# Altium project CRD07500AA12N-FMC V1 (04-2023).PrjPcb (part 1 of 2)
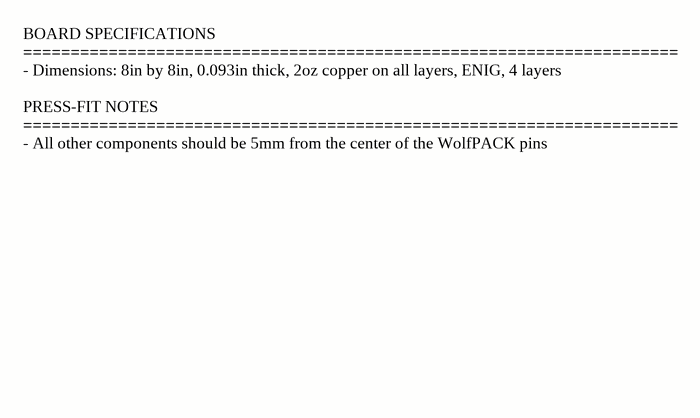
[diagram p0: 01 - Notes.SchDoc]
6 sheets, 393 parts. Net scope: global (net labels, ports and power ports of the same name join across sheets).
Board file: CRD07500AA12N-FMC V1 (04-2023).PcbDoc
Sheets:
  01 - Notes.SchDoc
  02 - Power Stage.SchDoc
  03 - Controller.SchDoc
  04 - Gate Drivers.SchDoc
  05 - Sense.SchDoc
  06 - Auxiliary Power.SchDoc

## Sheet 01 - Notes.SchDoc: 7.5kW WolfPACK FM3 Six-Pack Motor Drive
size 431 x 279 mm; Date: 04/2023; DocumentNumber: CRD07500AA12N-FMC; Revision: 1; SheetNumber: 1; SheetTotal: 6; SheetSize: B

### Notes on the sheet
- BOARD SPECIFICATIONS
  =====================================================================
  - Dimensions: 8in by 8in, 0.093in thick, 2oz copper on all layers, ENIG, 4 layers
  PRESS-FIT NOTES
  =====================================================================
  - All other components should be 5mm from the center of the WolfPACK pins

## Sheet 02 - Power Stage.SchDoc: Power Stage - 7.5kW WolfPACK Six-Pack M. Drive
size 431 x 279 mm; Date: 04/2023; DocumentNumber: CRD07500AA12N-FMC; Revision: 1; SheetNumber: 2; SheetTotal: 6; SheetSize: B
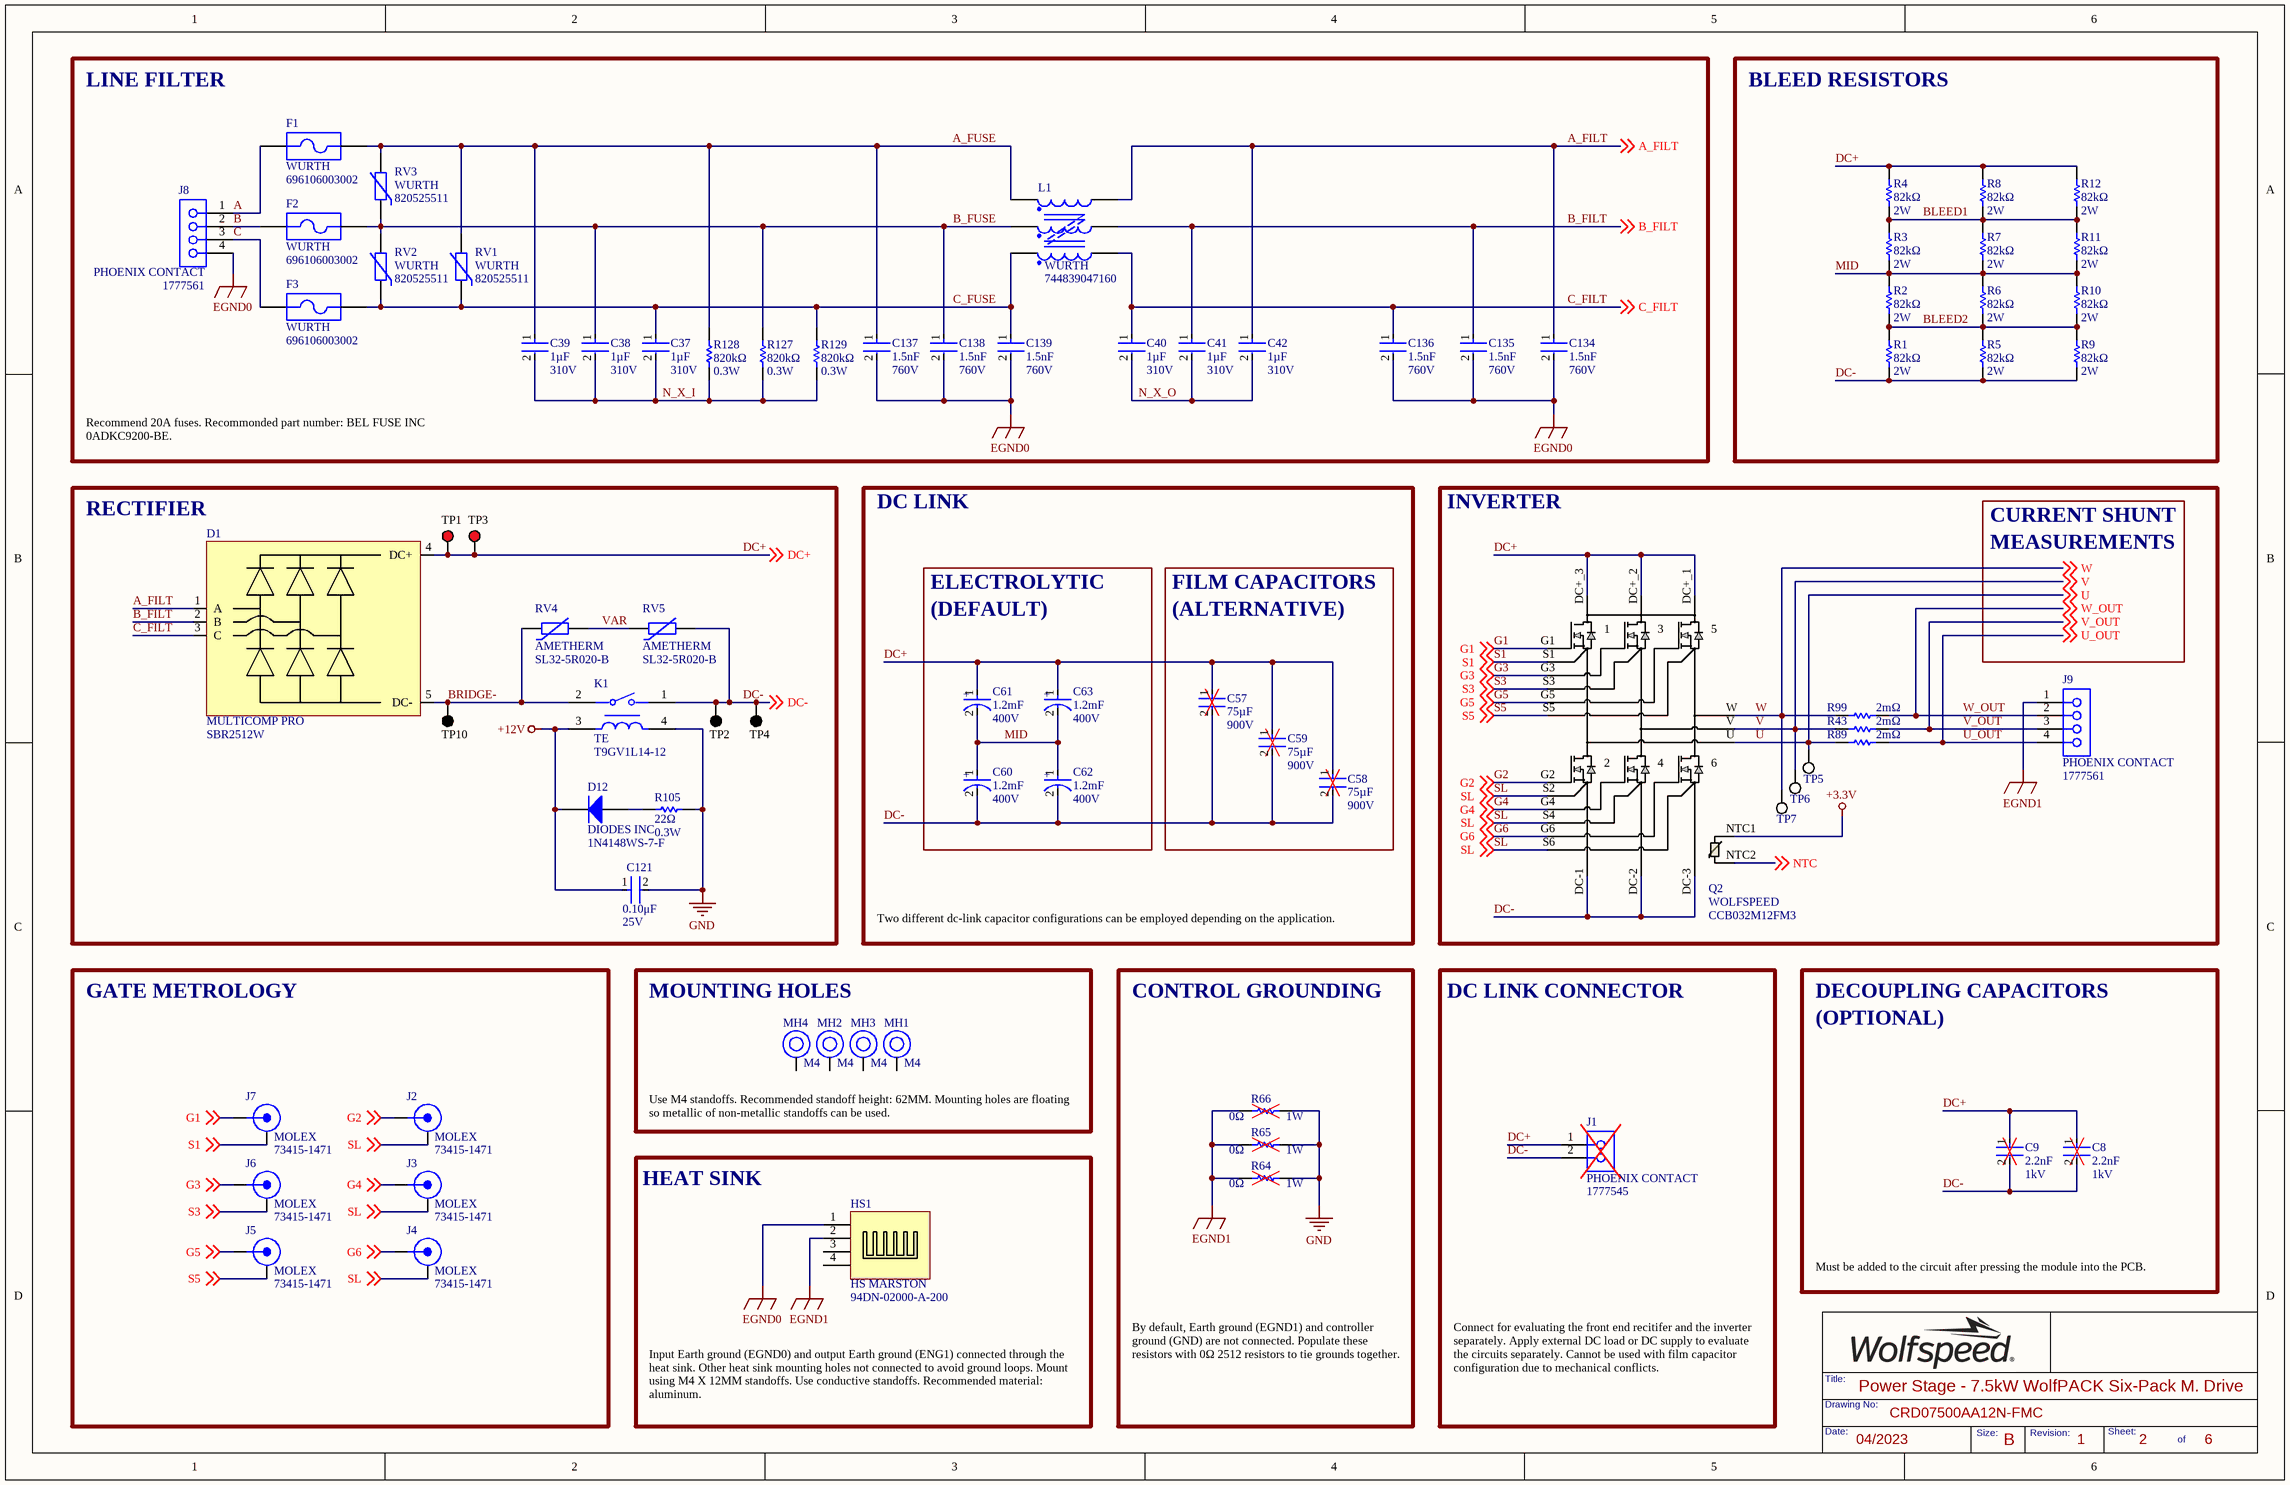
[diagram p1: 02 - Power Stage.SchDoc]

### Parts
C8  Capacitance: 2.2nF  Voltage Rating (DC): 1kV  [CAP_LDE_QD_1220_KEM]  (hidden comment: LDEQD1220KA5N00)
C9  Capacitance: 2.2nF  Voltage Rating (DC): 1kV  [CAP_LDE_QD_1220_KEM]  (hidden comment: LDEQD1220KA5N00)
C37  Capacitance: 1µF  Voltage Rating (AC): 310V  [WCAP-FTXX_L26W11H20_CS]  (hidden comment: 890334026027CS)
C38  Capacitance: 1µF  Voltage Rating (AC): 310V  [WCAP-FTXX_L26W11H20_CS]  (hidden comment: 890334026027CS)
C39  Capacitance: 1µF  Voltage Rating (AC): 310V  [WCAP-FTXX_L26W11H20_CS]  (hidden comment: 890334026027CS)
C40  Capacitance: 1µF  Voltage Rating (AC): 310V  [WCAP-FTXX_L26W11H20_CS]  (hidden comment: 890334026027CS)
C41  Capacitance: 1µF  Voltage Rating (AC): 310V  [WCAP-FTXX_L26W11H20_CS]  (hidden comment: 890334026027CS)
C42  Capacitance: 1µF  Voltage Rating (AC): 310V  [WCAP-FTXX_L26W11H20_CS]  (hidden comment: 890334026027CS)
C57  Capacitance: 75µF  Rated Voltage (DC): 900V  [WCAP-FTDB_L57W45H65]  (hidden comment: 75µF, 900V)
C58  Capacitance: 75µF  Rated Voltage (DC): 900V  [WCAP-FTDB_L57W45H65]  (hidden comment: 75µF, 900V)
C59  Capacitance: 75µF  Rated Voltage (DC): 900V  [WCAP-FTDB_L57W45H65]  (hidden comment: 75µF, 900V)
C60  Capacitance: 1.2mF  Voltage Rating: 400V  [B43630A9128M000]  (hidden comment: B43630A9128M000)
C61  Capacitance: 1.2mF  Voltage Rating: 400V  [B43630A9128M000]  (hidden comment: B43630A9128M000)
C62  Capacitance: 1.2mF  Voltage Rating: 400V  [B43630A9128M000]  (hidden comment: B43630A9128M000)
C63  Capacitance: 1.2mF  Voltage Rating: 400V  [B43630A9128M000]  (hidden comment: B43630A9128M000)
C121  Voltage Rating: 25V  Capacitance: 0.10μF  [FP-C0603C-CF-IPC_B]  (hidden comment: C0603C104K3RACTU)
C134  value 1.5nF  Voltage: 760V  [CAP_MY5UCR_VIS]  (hidden comment: SMDY1152MY5UCR)
C135  value 1.5nF  Voltage: 760V  [CAP_MY5UCR_VIS]  (hidden comment: SMDY1152MY5UCR)
C136  value 1.5nF  Voltage: 760V  [CAP_MY5UCR_VIS]  (hidden comment: SMDY1152MY5UCR)
C137  value 1.5nF  Voltage: 760V  [CAP_MY5UCR_VIS]  (hidden comment: SMDY1152MY5UCR)
C138  value 1.5nF  Voltage: 760V  [CAP_MY5UCR_VIS]  (hidden comment: SMDY1152MY5UCR)
C139  value 1.5nF  Voltage: 760V  [CAP_MY5UCR_VIS]  (hidden comment: SMDY1152MY5UCR)
D1  Manufacturer: MULTICOMP PRO  [SBR2512W]  (hidden comment: SBR2512W)
D12  Manufacturer: DIODES INC  [DIOD-SOD323-2-A_V]  (hidden comment: 1N4148WS-7-F)
F1  Manufacturer: WURTH  [696106003002]  (hidden comment: 696106003002)
F2  Manufacturer: WURTH  [696106003002]  (hidden comment: 696106003002)
F3  Manufacturer: WURTH  [696106003002]  (hidden comment: 696106003002)
HS1  Manufacturer: HS MARSTON  [94DN-02000-A-200]  (hidden comment: 94DN-02000-A-200)
J1  Manufacturer: PHOENIX CONTACT  [1777545]  (hidden comment: 1777545)
J2  Manufacturer: MOLEX  Manufacturer Part Number: 73415-1471  [FP-73415-1471-MFG]  (hidden comment: 0734151471)
J3  Manufacturer: MOLEX  Manufacturer Part Number: 73415-1471  [FP-73415-1471-MFG]  (hidden comment: 0734151471)
J4  Manufacturer: MOLEX  Manufacturer Part Number: 73415-1471  [FP-73415-1471-MFG]  (hidden comment: 0734151471)
J5  Manufacturer: MOLEX  Manufacturer Part Number: 73415-1471  [FP-73415-1471-MFG]  (hidden comment: 0734151471)
J6  Manufacturer: MOLEX  Manufacturer Part Number: 73415-1471  [FP-73415-1471-MFG]  (hidden comment: 0734151471)
J7  Manufacturer: MOLEX  Manufacturer Part Number: 73415-1471  [FP-73415-1471-MFG]  (hidden comment: 0734151471)
J8  Manufacturer: PHOENIX CONTACT  [1777561]  (hidden comment: 1777561)
J9  Manufacturer: PHOENIX CONTACT  [1777561]  (hidden comment: 1777561)
K1  Manufacturer: TE  [FP-T9GV1L14-12-MFG]  (hidden comment: T9GV1L14-12)
L1  Manufacturer: WURTH  [WE-TPB HV_Type 4XL_744839047160]  (hidden comment: 47mH)
MH1  Size: M4  [MH_M4_P]  (hidden comment: MH_M4_P)
MH2  Size: M4  [MH_M4_P]  (hidden comment: MH_M4_P)
MH3  Size: M4  [MH_M4_P]  (hidden comment: MH_M4_P)
MH4  Size: M4  [MH_M4_P]  (hidden comment: MH_M4_P)
Q2  CCB032M12FM3  Manufacturer: WOLFSPEED  [FM3_SIX-PACK_3PHASE_CRW]
R1  value 82kΩ  Power: 2W  [FP-CRGP2512-IPC_C]  (hidden comment: CRGP2512F82K)
R2  value 82kΩ  Power: 2W  [FP-CRGP2512-IPC_C]  (hidden comment: CRGP2512F82K)
R3  value 82kΩ  Power: 2W  [FP-CRGP2512-IPC_C]  (hidden comment: CRGP2512F82K)
R4  value 82kΩ  Power: 2W  [FP-CRGP2512-IPC_C]  (hidden comment: CRGP2512F82K)
R5  value 82kΩ  Power: 2W  [FP-CRGP2512-IPC_C]  (hidden comment: CRGP2512F82K)
R6  value 82kΩ  Power: 2W  [FP-CRGP2512-IPC_C]  (hidden comment: CRGP2512F82K)
R7  value 82kΩ  Power: 2W  [FP-CRGP2512-IPC_C]  (hidden comment: CRGP2512F82K)
R8  value 82kΩ  Power: 2W  [FP-CRGP2512-IPC_C]  (hidden comment: CRGP2512F82K)
R9  value 82kΩ  Power: 2W  [FP-CRGP2512-IPC_C]  (hidden comment: CRGP2512F82K)
R10  value 82kΩ  Power: 2W  [FP-CRGP2512-IPC_C]  (hidden comment: CRGP2512F82K)
R11  value 82kΩ  Power: 2W  [FP-CRGP2512-IPC_C]  (hidden comment: CRGP2512F82K)
R12  value 82kΩ  Power: 2W  [FP-CRGP2512-IPC_C]  (hidden comment: CRGP2512F82K)
R43  Resistance: 2mΩ  [FP-RC2512-0_65-MFG]  (hidden comment: CRE2512-FZ-R002E-3)
R64  Resistance: 0Ω  Max Power Dissipation: 1W  [FP-RC2512-0_65-IPC_A]  (hidden comment: RC2512JK-070RL)
R65  Resistance: 0Ω  Max Power Dissipation: 1W  [FP-RC2512-0_65-IPC_A]  (hidden comment: RC2512JK-070RL)
R66  Resistance: 0Ω  Max Power Dissipation: 1W  [FP-RC2512-0_65-IPC_A]  (hidden comment: RC2512JK-070RL)
R89  Resistance: 2mΩ  [FP-RC2512-0_65-MFG]  (hidden comment: CRE2512-FZ-R002E-3)
R99  Resistance: 2mΩ  [FP-RC2512-0_65-MFG]  (hidden comment: CRE2512-FZ-R002E-3)
R105  Resistance: 22Ω  Max Power Dissipation: 0.3W  [FP-CSR1206-IPC_A]  (hidden comment: RMCF1206FT22R0)
R127  Resistance: 820kΩ  Max Power Dissipation: 0.3W  [RESC3125X70X40LL20T20]  (hidden comment: KTR25JZPF8203)
R128  Resistance: 820kΩ  Max Power Dissipation: 0.3W  [RESC3125X70X40LL20T20]  (hidden comment: KTR25JZPF8203)
R129  Resistance: 820kΩ  Max Power Dissipation: 0.3W  [RESC3125X70X40LL20T20]  (hidden comment: KTR25JZPF8203)
RV1  Manufacturer: WURTH  [D23W10.1H27P3.4]  (hidden comment: 550VAC, 745VDC)
RV2  Manufacturer: WURTH  [D23W10.1H27P3.4]  (hidden comment: 550VAC, 745VDC)
RV3  Manufacturer: WURTH  [D23W10.1H27P3.4]  (hidden comment: 550VAC, 745VDC)
RV4  Manufacturer: AMETHERM  Manufacturer Part Number: SL32-5R020-B  [SL22 10008-B-Footprint-1]  (hidden comment: SL32 5R020-B)
RV5  Manufacturer: AMETHERM  Manufacturer Part Number: SL32-5R020-B  [SL22 10008-B-Footprint-1]  (hidden comment: SL32 5R020-B)
TP1  5010  [KSTN-5010_V]  (value not drawn)
TP2  5011  [KSTN-5011_V]  (value not drawn)
TP3  5010  [KSTN-5010_V]  (value not drawn)
TP4  5011  [KSTN-5011_V]  (value not drawn)
TP5  5012  [KSTN-5012_V]  (value not drawn)
TP6  5012  [KSTN-5012_V]  (value not drawn)
TP7  5012  [KSTN-5012_V]  (value not drawn)
TP10  5011  [KSTN-5011_V]  (value not drawn)

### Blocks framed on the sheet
LINE FILTER: C37-C42 C134-C139 F1-F3 J8 L1 R127-R129 RV1-RV3
BLEED RESISTORS: R1-R12
RECTIFIER: C121 D1 D12 K1 R105 RV4 RV5 TP1-TP4 TP10
GATE METROLOGY: J2-J7
MOUNTING HOLES: MH1-MH4
CONTROL GROUNDING: R64-R66
DC LINK CONNECTOR: J1
HEAT SINK: HS1

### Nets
+3.3V: Q2.NTC1
+12V: C121.1 D12.2(K) K1.3
EGND0: C134.2 C135.2 C136.2 C137.2 C138.2 C139.2 HS1.1 J8.4
EGND1: HS1.2 J9.1 R64.1 R65.1 R66.1
GND: C121.2 K1.4 R64.2 R65.2 R66.2 R105.2
A: F1.1 J8.1
A_FILT: C42.1 C134.1 D1.1(A) L1.4 ; off-sheet A_FILT
A_FUSE: C39.1 C137.1 F1.2 L1.1 R128.2 RV1.2 RV3.2
B: F2.1 J8.2
B_FILT: C41.1 C135.1 D1.2(B) L1.5 ; off-sheet B_FILT
B_FUSE: C38.1 C138.1 F2.2 L1.2 R127.2 RV2.2 RV3.1
BLEED1: R3.2 R4.1 R7.2 R8.1 R11.2 R12.1
BLEED2: R1.2 R2.1 R5.2 R6.1 R9.2 R10.1
BRIDGE-: D1.5(DC-) K1.2 RV4.1 TP10.1
C: F3.1 J8.3
C_FILT: C40.1 C136.1 D1.3(C) L1.6 ; off-sheet C_FILT
C_FUSE: C37.1 C139.1 F3.2 L1.3 R129.2 RV1.1 RV2.1
DC+: C8.1 C9.1 C57.1 C58.1 C59.1 C61.1 C63.1 D1.4(DC+) J1.1 Q2.DC+_1 Q2.DC+_2 Q2.DC+_3 R4.2 R8.2 R12.2 TP1.1 TP3.1 ; off-sheet DC+
DC-: C8.2 C9.2 C57.2 C58.2 C59.2 C60.2 C62.2 J1.2 K1.1 Q2.DC-1 Q2.DC-2 Q2.DC-3 R1.1 R5.1 R9.1 RV5.2 TP2.1 TP4.1 ; off-sheet DC-
G1: J7.1(CENTER) Q2.G1 ; off-sheet G1
G2: J2.1(CENTER) Q2.G2 ; off-sheet G2
G3: J6.1(CENTER) Q2.G3 ; off-sheet G3
G4: J3.1(CENTER) Q2.G4 ; off-sheet G4
G5: J5.1(CENTER) Q2.G5 ; off-sheet G5
G6: J4.1(CENTER) Q2.G6 ; off-sheet G6
MID: C60.1 C61.2 C62.1 C63.2 R2.2 R3.1 R6.2 R7.1 R10.2 R11.1
N_X_I: C37.2 C38.2 C39.2 R127.1 R128.1 R129.1
N_X_O: C40.2 C41.2 C42.2
NTC: Q2.NTC2 ; off-sheet NTC
S1: J7.2,3,4,5(SHIELD) Q2.S1 ; off-sheet S1
S3: J6.2,3,4,5(SHIELD) Q2.S3 ; off-sheet S3
S5: J5.2,3,4,5(SHIELD) Q2.S5 ; off-sheet S5
SL: J2.2,3,4,5(SHIELD) J3.2,3,4,5(SHIELD) J4.2,3,4,5(SHIELD) Q2.S2 Q2.S4 Q2.S6 ; off-sheet SL
U: Q2.U R89.1 TP5.1 ; off-sheet U
U_OUT: J9.4 R89.2 ; off-sheet U_OUT
V: Q2.V R43.1 TP6.1 ; off-sheet V
V_OUT: J9.3 R43.2 ; off-sheet V_OUT
VAR: RV4.2 RV5.1
W: Q2.W R99.1 TP7.1 ; off-sheet W
W_OUT: J9.2 R99.2 ; off-sheet W_OUT
NetD12_1: D12.1(A) R105.1

Not connected (* = marked no-connect by the designer): HS1 3 4; MH1 1; MH2 1; MH3 1; MH4 1

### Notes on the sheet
- Recommend 20A fuses. Recommonded part number: BEL FUSE INC 0ADKC9200-BE.
- DC LINK
- INVERTER
- CURRENT SHUNT
- MEASUREMENTS
- ELECTROLYTIC
- (DEFAULT)
- FILM CAPACITORS
- (ALTERNATIVE)
- Two different dc-link capacitor configurations can be employed depending on the application.
- DECOUPLING CAPACITORS
- (OPTIONAL)
- Use M4 standoffs. Recommended standoff height: 62MM. Mounting holes are floating so metallic of non-metallic standoffs can be used.
- Must be added to the circuit after pressing the module into the PCB.
- Input Earth ground (EGND0) and output Earth ground (ENG1) connected through the heat sink. Other heat sink mounting holes not connected to avoid ground loops. Mount using M4 X 12MM standoffs. Use conductive standoffs. Recommended material: aluminum.
- By default, Earth ground (EGND1) and controller ground (GND) are not connected. Populate these resistors with 0Ω 2512 resistors to tie grounds together.
- Connect for evaluating the front end recitifer and the inverter separately. Apply external DC load or DC supply to evaluate the circuits separately. Cannot be used with film capacitor configuration due to mechanical conflicts.

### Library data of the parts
C8 C9 = LDEQD1220KA5N00: CAP FILM 2200PF 10% 1KVDC 2220; Manufacturer: KEMET; Dielectric Material: Polyester; Voltage Rating (AC): 250V; Value: 2.2nF
C37-C42 = 890334026027CS: CAP FILM 1UF 10% 310VAC RADIAL; Manufacturer: WURTH; Dielectric Material: PP; Ratings: X2; Value: 1µF
C57-C59 = 890724429010CS: WCAP-FTDB DC-LINK CAPACITOR (MKP; Manufacturer: WURTH; Dissipation Factor @1kHz: 0.31%; Insulation Resistance: 133.33MΩ; Pitch: 52.5mm; Rate of Voltage Rise: 15V/µs; Technical Reference: MDBP525756J900DCPP15040
C60-C63 = B43630A9128M000: CAP ALUM 1200UF 20% 400V SNAP; Manufacturer: TDK; Polarity: Polar; ESR (Equivalent Series Resistance): 100mR; Life (Hours): 2000Hour; Impedance: 170mR; Value: 1.2mF
C121 = CMP-2006-03057-2: CAP CER 0.1UF 25V X7R 0603; Manufacturer: KEMET; Value: 0.10μF; Material: Ceramic; Tolerance: 0.1; Temperature Coefficient: 30ppm/°C; Automotive Grade: Grade 1
C134-C139 = SMDY1152MY5UCR: SMDY1 X760Y500VAC 1500PF 20% Y5U; Manufacturer: VISHAY; Description: Ceramic Suppression Cap, 1500PF, X1/Y1 Rohs Compliant: Yes
D1 = SBR2512W: BRIDGE RECT 3P 1.2KV 25A
D12 = CMP-1667-00004-1: DIODE GEN PURP 75V 150MA SOD323
F1-F3 = CMP-1502-00235-1: FUSEHOLDER BLOCKS - PCB - CLIP C; Fuse Size: 5x20mm
HS1 = 94DN-02000-A-200: HEATSINK EXTRUSION 200MM; Natural Thermal Resistance: 0.7°C/W
J1 = 1777545: TERM BLK 2P SIDE ENT 6.35MM PCB; Voltage Rating: 1kV; Voltage: 600V; Current Rating: 41A; Number of Levels: 1; Number of Positions Per Level: 2; Current: 30A; Gender: Male; Connector Type: Screw; Wire Gauge (Max): 30AWG; Wire Gauge (Min): 10AWG; Approvals: cULus,EAC
J2-J7 = 0734151471: CONN MMCX JACK STR 50 OHM PCB; Body Material: Brass; Body Plating: Gold; Impedance: 50R; Connector Type: PCB,MMCX,Coaxial; Max Frequency: 6GHz; Gender: Female
J8 J9 = 1777561: TERM BLK 4P SIDE ENT 6.35MM PCB; Current Rating: 41A; Number of Positions: 4; Voltage Rating: 1kV; Number of Levels: 1; Current: 30A; Voltage: 600V; Wire Gauge (Max): 30AWG; Wire Gauge (Min): 10AWG
K1 = CMP-03395-000345-1: RELAY GEN PURPOSE SPST 30A 12V; Operate Time: 15ms; Coil Power: 900mW; Release Time: 22ms; Coil Resistance: 160R; Relay Type: General Purpose; Coil Type: Non-Latching; Coil Current: 75mA
L1 = 744839047160: CMC 47MH 16A 3LN TH; Match Code: WE-TPB HV; Case/Size Code: Type 4XL; DC Resistance Max: 14mΩ; Insulation Test Voltage (AC): 3000V; Material: MnZn; Rated Voltage (AC): 760V
MH1-MH4 = MH_M4_P: HEX STANDOFF M4 ALUMINUM 31MM F-F; Manufacturer: MCMASTER-CARR; Manufacturer Part Number: 95947A065
Q2 = CCB032M12FM3: 1200V SIC 6-PACK MODULE; Type: DEV
R1-R12 = CRGP2512F82K: RES 82K OHM 1% 2W 2512; Manufacturer: TE
R43 R89 R99 = CRE2512-FZ-R002E-3: RES 0.002 OHM 1% 3W 2512; Manufacturer: BOURNS; Temperature Coefficient: 75ppm/°C; Value: 2mΩ
R64-R66 = RC2512JK-070RL: RES 0 OHM JUMPER 1W 2512; Manufacturer: YAGEO; Tolerance: 5%; Temperature Coefficient: 200ppm/°C; Voltage Rating: 200V; Value: 0Ω
R105 = RMCF1206FT22R0: RES 22 OHM 1% 1/4W 1206; Manufacturer: STACKPOLE; Temperature Coefficient: 100ppm/°C; Value: 22Ω
R127-R129 = KTR25JZPF8203: RES SMD 820K OHM 1% 1/3W 1210; Manufacturer: ROHM; Temperature Coefficient: 100ppm/°C; Value: 820kΩ
RV1-RV3 = 820525511: DISK VARISTOR STANDARD WE-VD - B; Channel Input Capacitance: 430pF; Clamping Voltage: 1500V; Energy Absorption: 408J; Operating Voltage (AC): 550V; Operating Voltage (DC): 745V; Pitch: 3.4mm; Power Dissipation: 1W; (Reverse) Breakdown Voltage: 910V; (Reverse) Peak Pulse Current: 6500A
RV4 RV5 = SL32 5R020-B: ICL 5 OHM 20% 20A 31MM; Resistance: 5R; Dissipation Factor: 45.4%; Lead Diameter: 1mm; Approvals: CSA,UR; Value: 5Ω
TP1 TP3 = CMP-1672-00002-4: PC TEST POINT MULTIPURPOSE RED; Manufacturer: KEYSTONE
TP2 TP4 TP10 = CMP-1672-00003-4: PC TEST POINT MULTIPURPOSE BLACK; Manufacturer: KEYSTONE
TP5-TP7 = CMP-1672-00004-4: PC TEST POINT MULTIPURPOSE WHITE; Manufacturer: KEYSTONE

## Sheet 03 - Controller.SchDoc: Controller - 7.5kW WolfPACK FM3 Six-Pack M. Drive
size 431 x 279 mm; Date: 04/2023; DocumentNumber: CRD07500AA12N-FMC; Revision: 1; SheetNumber: 3; SheetTotal: 6; SheetSize: B
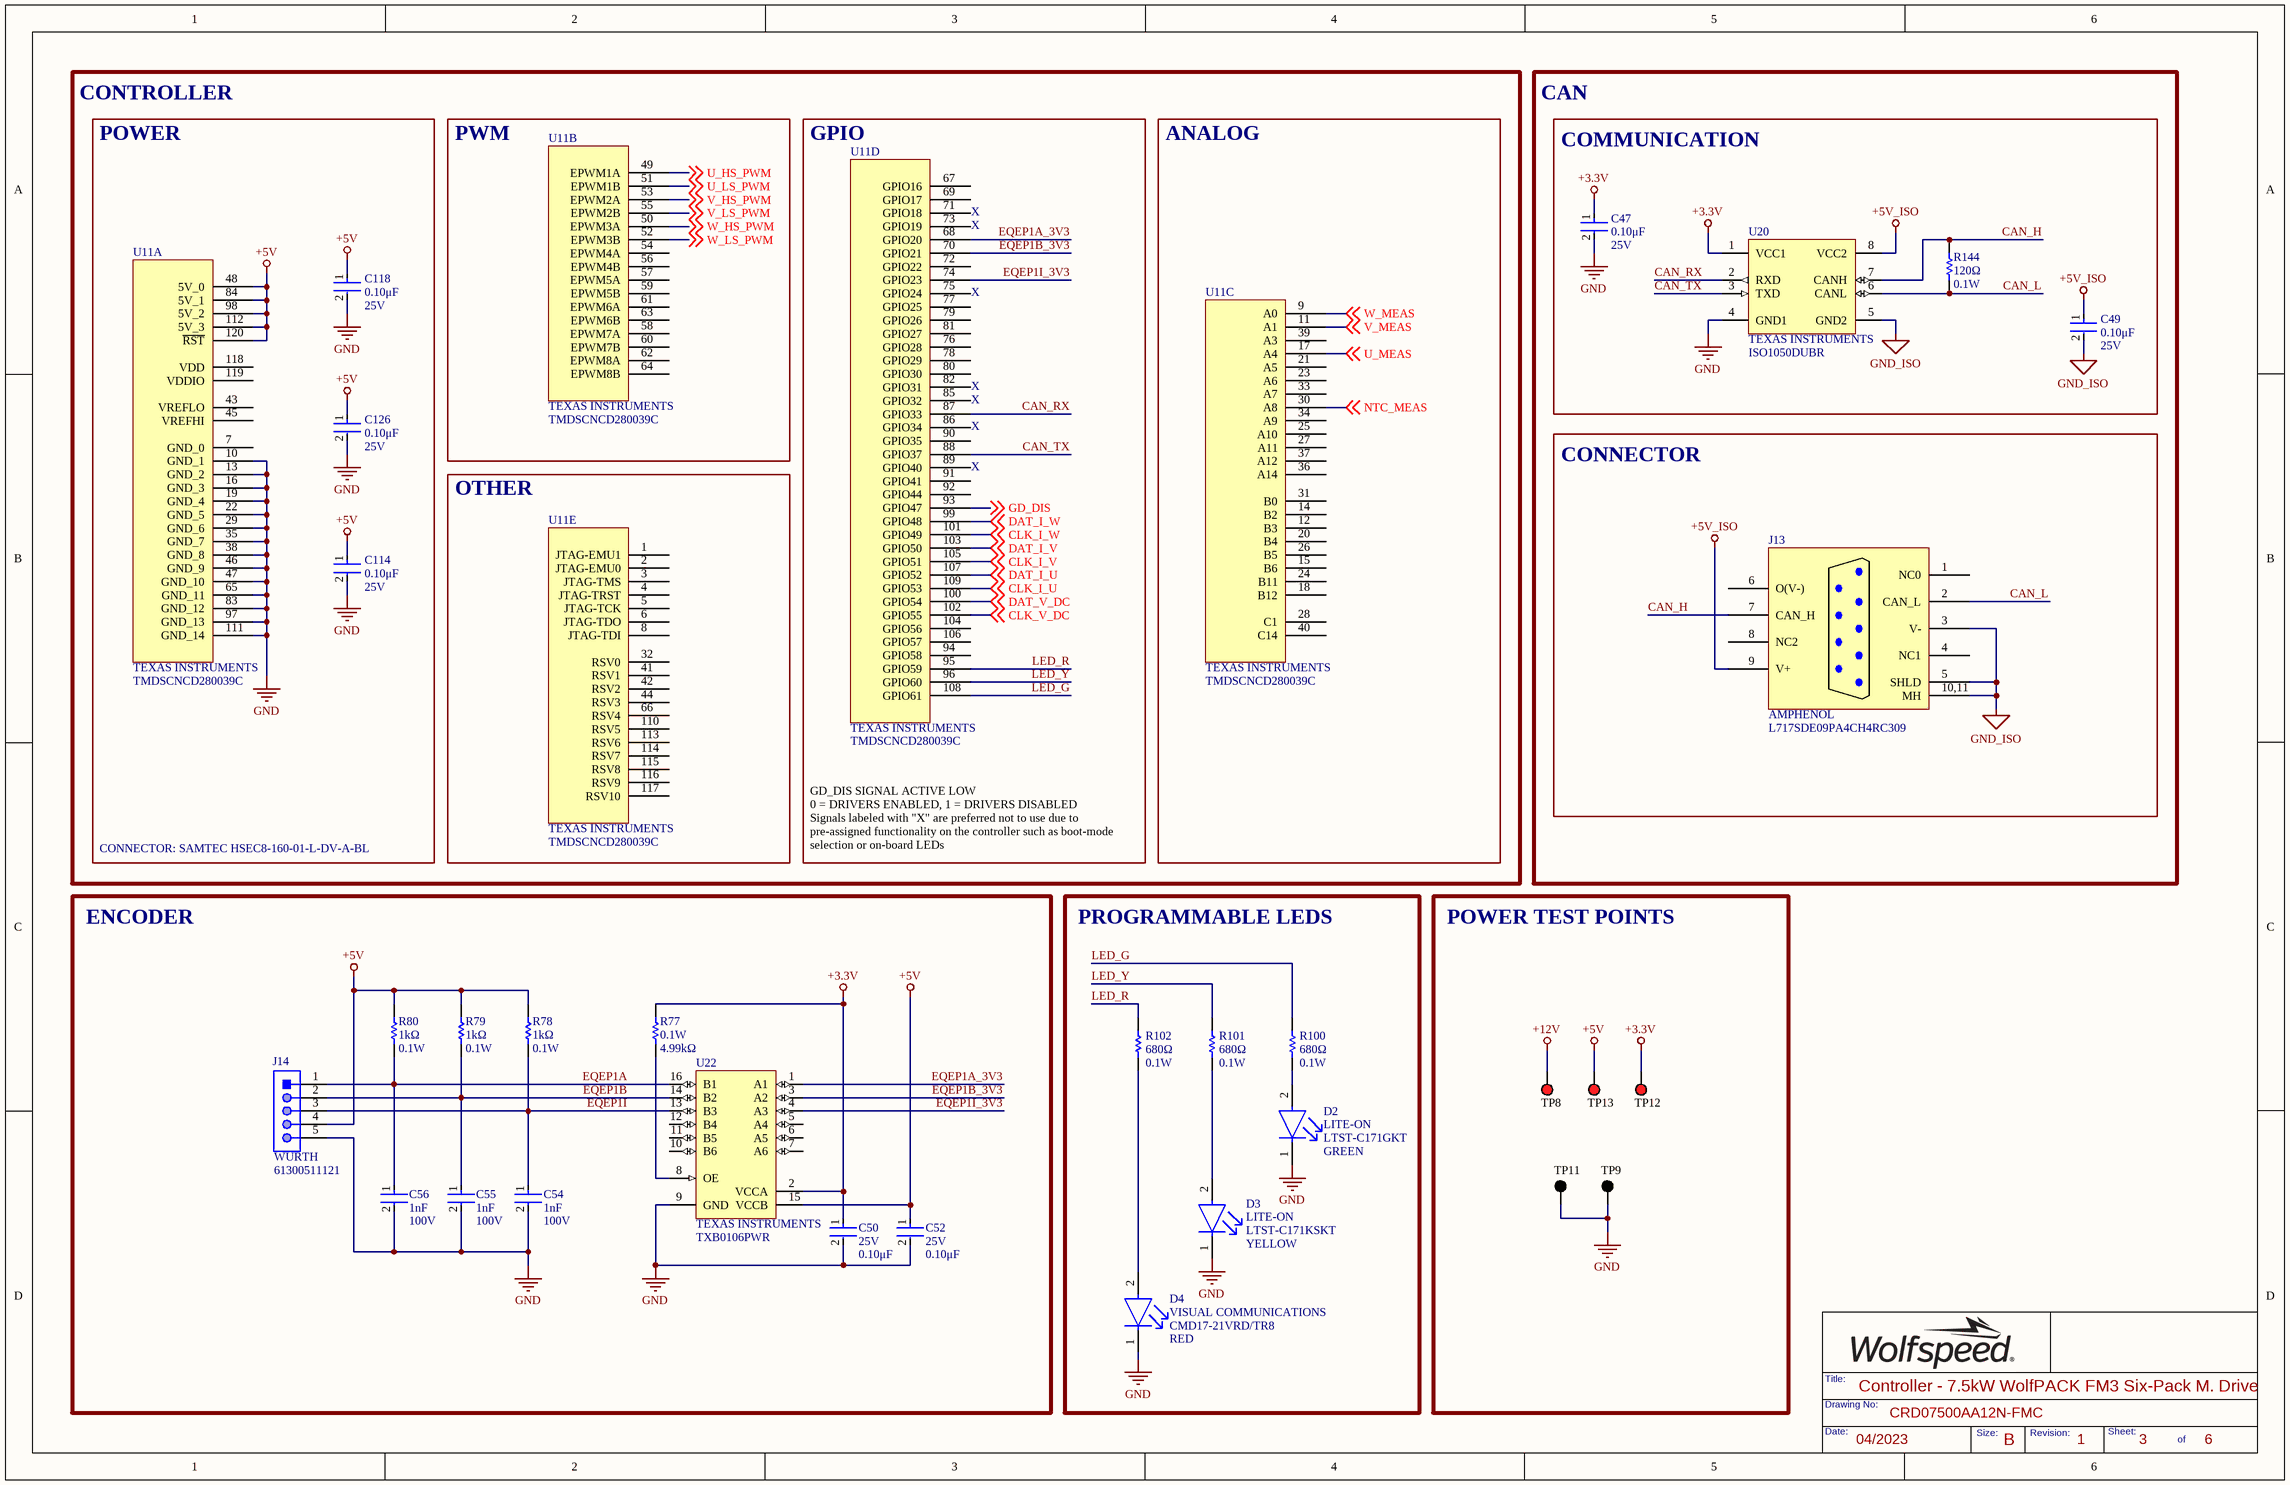
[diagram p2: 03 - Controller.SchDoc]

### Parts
C47  Voltage Rating: 25V  Capacitance: 0.10μF  [FP-C0603C-CF-IPC_B]  (hidden comment: C0603C104K3RACTU)
C49  Voltage Rating: 25V  Capacitance: 0.10μF  [FP-C0603C-CF-IPC_B]  (hidden comment: C0603C104K3RACTU)
C50  Voltage Rating: 25V  Capacitance: 0.10μF  [FP-C0603C-CF-IPC_B]  (hidden comment: C0603C104K3RACTU)
C52  Voltage Rating: 25V  Capacitance: 0.10μF  [FP-C0603C-CF-IPC_B]  (hidden comment: C0603C104K3RACTU)
C54  Capacitance: 1nF  Voltage Rating: 100V  [FP-C0603C-CF-IPC_B]  (hidden comment: C0603C102J1GACTU)
C55  Capacitance: 1nF  Voltage Rating: 100V  [FP-C0603C-CF-IPC_B]  (hidden comment: C0603C102J1GACTU)
C56  Capacitance: 1nF  Voltage Rating: 100V  [FP-C0603C-CF-IPC_B]  (hidden comment: C0603C102J1GACTU)
C114  Voltage Rating: 25V  Capacitance: 0.10μF  [FP-C0603C-CF-IPC_B]  (hidden comment: C0603C104K3RACTU)
C118  Voltage Rating: 25V  Capacitance: 0.10μF  [FP-C0603C-CF-IPC_B]  (hidden comment: C0603C104K3RACTU)
C126  Voltage Rating: 25V  Capacitance: 0.10μF  [FP-C0603C-CF-IPC_B]  (hidden comment: C0603C104K3RACTU)
D2  value GREEN  Manufacturer: LITE-ON  [FP-LTST-C171GKT-MFG]  (hidden comment: LTST-C171GKT)
D3  LTST-C171KSKT  Manufacturer: LITE-ON  Color Print: YELLOW  [FP-LTST-C171GKT-MFG-YELLOW]
D4  value RED  Manufacturer: VISUAL COMMUNICATIONS  [FP-LTST-C171GKT-MFG-RED]  (hidden comment: CMD17-21VRD/TR8)
J13  Manufacturer: AMPHENOL  [L717SDE09PA4CH4RC309]  (hidden comment: L717SDE09PA4CH4RC309)
J14  Manufacturer: WURTH  [61300511121]  (hidden comment: 61300511121)
R77  Power Rating: 0.1W  Resistance: 4.99kΩ  [FP-MCR03-IPC_B]  (hidden comment: RC0603FR-074K99L)
R78  Resistance: 1kΩ  Power Rating: 0.1W  [FP-MCR03-IPC_B]  (hidden comment: RT0603DRD071KL)
R79  Resistance: 1kΩ  Power Rating: 0.1W  [FP-MCR03-IPC_B]  (hidden comment: RT0603DRD071KL)
R80  Resistance: 1kΩ  Power Rating: 0.1W  [FP-MCR03-IPC_B]  (hidden comment: RT0603DRD071KL)
R100  Power Rating: 0.1W  Resistance: 680Ω  [FP-MCR03-IPC_B]  (hidden comment: RC0603FR-07680RL)
R101  Power Rating: 0.1W  Resistance: 680Ω  [FP-MCR03-IPC_B]  (hidden comment: RC0603FR-07680RL)
R102  Power Rating: 0.1W  Resistance: 680Ω  [FP-MCR03-IPC_B]  (hidden comment: RC0603FR-07680RL)
R144  Resistance: 120Ω  Max Power Dissipation: 0.1W  [FP-MCR03-IPC_B]  (hidden comment: RC0603JR-07120RL)
TP8  5010  [KSTN-5010_V]  (value not drawn)
TP9  5011  [KSTN-5011_V]  (value not drawn)
TP11  5011  [KSTN-5011_V]  (value not drawn)
TP12  5010  [KSTN-5010_V]  (value not drawn)
TP13  5010  [KSTN-5010_V]  (value not drawn)
U11  Manufacturer: TEXAS INSTRUMENTS  [TMDSCNCD280039C]  (hidden comment: TMDSCNCD280039C)  (parts A,B,C,D,E of 5)
U20  Manufacturer: TEXAS INSTRUMENTS  [DUB0008A_M]  (hidden comment: ISO1050DUBR)
U22  TXB0106PWR  Manufacturer: TEXAS INSTRUMENTS  [PW0016A_L]

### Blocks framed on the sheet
POWER: C114 C118 C126 U11
PWM: U11
GPIO: U11
ANALOG: U11
COMMUNICATION: C47 C49 R144 U20
CONNECTOR: J13
OTHER: U11
ENCODER: C50 C52 C54-C56 J14 R77-R80 U22
PROGRAMMABLE LEDS: D2-D4 R100-R102
POWER TEST POINTS: TP8 TP9 TP11-TP13

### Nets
+3.3V: C47.1 C50.1 R77.2 TP12.1 U20.1(VCC1) U22.2(VCCA)
+5V: C52.1 C114.1 C118.1 C126.1 J14.4 R78.2 R79.2 R80.2 TP13.1 U11.48(5V_0) U11.84(5V_1) U11.98(5V_2) U11.112(5V_3) U11.120(~{RST}) U22.15(VCCB)
+5V_ISO: C49.1 J13.9(V+) U20.8(VCC2)
+12V: TP8.1
GND: C47.2 C50.2 C52.2 C54.2 C55.2 C56.2 C114.2 C118.2 C126.2 D2.1(C) D3.1(C) D4.1(C) J14.5 TP9.1 TP11.1 U11.10(GND_1) U11.13(GND_2) U11.16(GND_3) U11.19(GND_4) U11.22(GND_5) U11.29(GND_6) U11.35(GND_7) U11.38(GND_8) U11.46(GND_9) U11.47(GND_10) U11.65(GND_11) U11.83(GND_12) U11.97(GND_13) U11.111(GND_14) U20.4(GND1) U22.9(GND)
GND_ISO: C49.2 J13.3(V-) J13.5(SHLD) J13.10,11(MH) U20.5(GND2)
CAN_H: J13.7(CAN_H) R144.2 U20.7(CANH)
CAN_L: J13.2(CAN_L) R144.1 U20.6(CANL)
CAN_RX: U11.87(GPIO33) U20.2(RXD)
CAN_TX: U11.88(GPIO37) U20.3(TXD)
CLK_I_U: U11.109(GPIO53) ; off-sheet CLK_I_U
CLK_I_V: U11.105(GPIO51) ; off-sheet CLK_I_V
CLK_I_W: U11.101(GPIO49) ; off-sheet CLK_I_W
CLK_V_DC: U11.102(GPIO55) ; off-sheet CLK_V_DC
DAT_I_U: U11.107(GPIO52) ; off-sheet DAT_I_U
DAT_I_V: U11.103(GPIO50) ; off-sheet DAT_I_V
DAT_I_W: U11.99(GPIO48) ; off-sheet DAT_I_W
DAT_V_DC: U11.100(GPIO54) ; off-sheet DAT_V_DC
EQEP1A: C56.1 J14.1 R80.1 U22.16(B1)
EQEP1A_3V3: U11.68(GPIO20) U22.1(A1)
EQEP1B: C55.1 J14.2 R79.1 U22.14(B2)
EQEP1B_3V3: U11.70(GPIO21) U22.3(A2)
EQEP1I: C54.1 J14.3 R78.1 U22.13(B3)
EQEP1I_3V3: U11.74(GPIO23) U22.4(A3)
GD_DIS: U11.93(GPIO47) ; off-sheet GD_DIS
LED_G: R100.2 U11.108(GPIO61)
LED_R: R102.2 U11.95(GPIO59)
LED_Y: R101.2 U11.96(GPIO60)
NTC_MEAS: U11.30(A8) ; off-sheet NTC_MEAS
U_HS_PWM: U11.49(EPWM1A) ; off-sheet U_HS_PWM
U_LS_PWM: U11.51(EPWM1B) ; off-sheet U_LS_PWM
U_MEAS: U11.17(A4) ; off-sheet U_MEAS
V_HS_PWM: U11.53(EPWM2A) ; off-sheet V_HS_PWM
V_LS_PWM: U11.55(EPWM2B) ; off-sheet V_LS_PWM
V_MEAS: U11.11(A1) ; off-sheet V_MEAS
W_HS_PWM: U11.50(EPWM3A) ; off-sheet W_HS_PWM
W_LS_PWM: U11.52(EPWM3B) ; off-sheet W_LS_PWM
W_MEAS: U11.9(A0) ; off-sheet W_MEAS
NetD2_2: D2.2(A) R100.1
NetD3_2: D3.2(A) R101.1
NetD4_2: D4.2(A) R102.1
NetR77_1: R77.1 U22.8(OE)

Not connected (* = marked no-connect by the designer): J13 1(NC0) 4(NC1) 6(O(V-)) 8(NC2); U11 1(JTAG-EMU1) 2(JTAG-EMU0) 3(JTAG-TMS) 4(JTAG-TRST) 5(JTAG-TCK) 6(JTAG-TDO) 7(GND_0) 8(JTAG-TDI) 12(B3) 14(B2) 15(B6) 18(B12) 20(B4) 21(A5) 23(A6) 24(B11) 25(A10) 26(B5) 27(A11) 28(C1) 31(B0) 32(RSV0) 33(A7) 34(A9) 36(A14) 37(A12) 39(A3) 40(C14) 41(RSV1) 42(RSV2) 43(VREFLO) 44(RSV3) 45(VREFHI) 54(EPWM4A) 56(EPWM4B) 57(EPWM5A) 58(EPWM7A) 59(EPWM5B) 60(EPWM7B) 61(EPWM6A) 62(EPWM8A) 63(EPWM6B) 64(EPWM8B) 66(RSV4) 67(GPIO16) 69(GPIO17) 71(GPIO18) 72(GPIO22) 73(GPIO19) 75(GPIO24) 76(GPIO28) 77(GPIO25) 78(GPIO29) 79(GPIO26) 80(GPIO30) 81(GPIO27) 82(GPIO31) 85(GPIO32) 86(GPIO34) 89(GPIO40) 90(GPIO35) 91(GPIO41) 92(GPIO44) 94(GPIO58) 104(GPIO56) 106(GPIO57) 110(RSV5) 113(RSV6) 114(RSV7) 115(RSV8) 116(RSV9) 117(RSV10) 118(VDD) 119(VDDIO); U22 5(A4) 6(A5) 7(A6) 10(B6) 11(B5) 12(B4)

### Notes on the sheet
- CONTROLLER
- CAN
- (near U11) X
- CONNECTOR: SAMTEC HSEC8-160-01-L-DV-A-BL
- GD_DIS SIGNAL ACTIVE LOW
  0 = DRIVERS ENABLED, 1 = DRIVERS DISABLED
  Signals labeled with "X" are preferred not to use due to pre-assigned functionality on the controller such as boot-mode selection or on-board LEDs

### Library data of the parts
C47 C49 C50 C52 C114 C118 C126 = CMP-2006-03057-2: as C121 on sheet 02 - Power Stage
C54-C56 = CMP-2006-03341-2: CAP CER 1000PF 100V C0G/NP0 0603; Manufacturer: KEMET; Material: Ceramic; Value: 1nF; Automotive Grade: Grade 1; Temperature Coefficient: 30ppm/°C; Temperature Characteristic: C0G; Tolerance: 0.05
D2 = CMP-22017-000007-1: LED GREEN CLEAR CHIP SMD; Luminous Intensity: 12mcd; Lens Color: Colorless; Dominant Wavelength: 569nm; Number of LEDs: 1; Power Dissipation: 100mW; Viewing Angle: 130°; Reverse Voltage: 5V; Test Current: 10mA; Forward Voltage: 2.1V; Wavelength: 585nm; Lens Style: Diffused; Forward Current: 30mA
D3 = LTST-C171KSKT: LED YELLOW CLEAR 0805 SMD; Lens Color: Colorless; Number of LEDs: 1; Reverse Voltage: 5V; Viewing Angle: 130°; Lens Style: Diffused,Colorless,Rectangular,Clear; Luminous Intensity: 50mcd; Forward Voltage: 2V; Dominant Wavelength: 587nm; Test Current: 20mA; Wavelength: 588nm; Forward Current: 30mA; Max Power Dissipation: 75mW
D4 = CMD17-21VRD/TR8: LED RED DIFFUSED 0805 SMD; Power Rating: 100mW; Luminous Intensity: 6mcd; Viewing Angle: 140°; Lens Style: Diffused,Tinted,Rectangular,Colored; Forward Current: 20mA; Forward Voltage: 2V; Wavelength: 640nm; Reverse Voltage (DC): 5V; Number of LEDs: 1
J13 = L717SDE09PA4CH4RC309: CONN D-SUB PLUG 9POS R/A SLDR; Number of Terminals/Pins: 9; Connector Type: D-Sub,Plug; Voltage Rating: 250V; Current Rating: 5A; Number of Ports: 1; Pitch: 2.74mm
J14 = CMP-1502-01068-1: CONN HEADER VERT 5POS 2.54MM; Row Number: Single; Pin Number: 5; Contact Resistance: 20mOhm; Working Voltage: 250VAC; Withstanding Voltage: 500VAC; Rated Current: 3A; Gender: Male
R77 = RC0603FR-074K99L: RES 4.99K OHM 1% 1/10W 0603; Manufacturer: YAGEO; Voltage Rating: 75V; Temperature Coefficient: 100ppm/°C; Voltage Rating (DC): 50V; Value: 4.99kΩ
R78-R80 = RT0603DRD071KL: RES SMD 1K OHM 0.5% 1/10W 0603; Manufacturer: YAGEO; Temperature Coefficient: 25ppm/°C; Max Power Dissipation: 100mW; Voltage Rating (DC): 50V; Voltage Rating: 75V; Value: 1kΩ
R100-R102 = RC0603FR-07680RL: RES 680 OHM 1% 1/10W 0603; Manufacturer: YAGEO; Voltage Rating (DC): 50V; Temperature Coefficient: 100ppm/°C; Max Power Dissipation: 100mW; Value: 680Ω
R144 = RC0603JR-07120RL: RES SMD 120 OHM 5% 1/10W 0603; Manufacturer: YAGEO; Voltage Rating (DC): 50V; Temperature Coefficient: 100ppm/°C; Power Rating: 100mW; Value: 120Ω
TP8 TP12 TP13 = CMP-1672-00002-4: as TP1 on sheet 02 - Power Stage
TP9 TP11 = CMP-1672-00003-4: as TP2 on sheet 02 - Power Stage
U11 = TMDSCNCD280039C: EVAL BOARD FOR TMS320F280039C
U20 = ISO1050DUBR: IC TXRX/ISO HALF 1/1 8SOP; Rating: Catalog; Eco-Plan: Green (RoHS & no Sb/Br); Isolated: Yes; Drivers Per Package: 1; SubFamily: CAN
U22 = CMP-2000-07336-1: IC TRANSLATOR BIDIR 16TSSOP; Dynamic Catalog: TXBSeries; Differential - Input: Output:No/No; Number of Bits: 6; Output Type: Logic; Propagation Delay (Max): 4ns; Number of Outputs/Channel: 1; Voltage - Supply: 1.2V~3.6V,1.65V~5.5V; Data Rate: 100Mbps; Product Training Modules: VoltageLevelTranslation; Other Names: 296-23759-1; Logic Function: Translator,Bidirectional

## Sheet 04 - Gate Drivers.SchDoc: Gate Drivers - 7.5kW WolfPACK Six-Pack M. Drive
size 431 x 279 mm; Date: 04/2023; DocumentNumber: CRD07500AA12N-FMC; Revision: 1; SheetNumber: 4; SheetTotal: 6; SheetSize: B
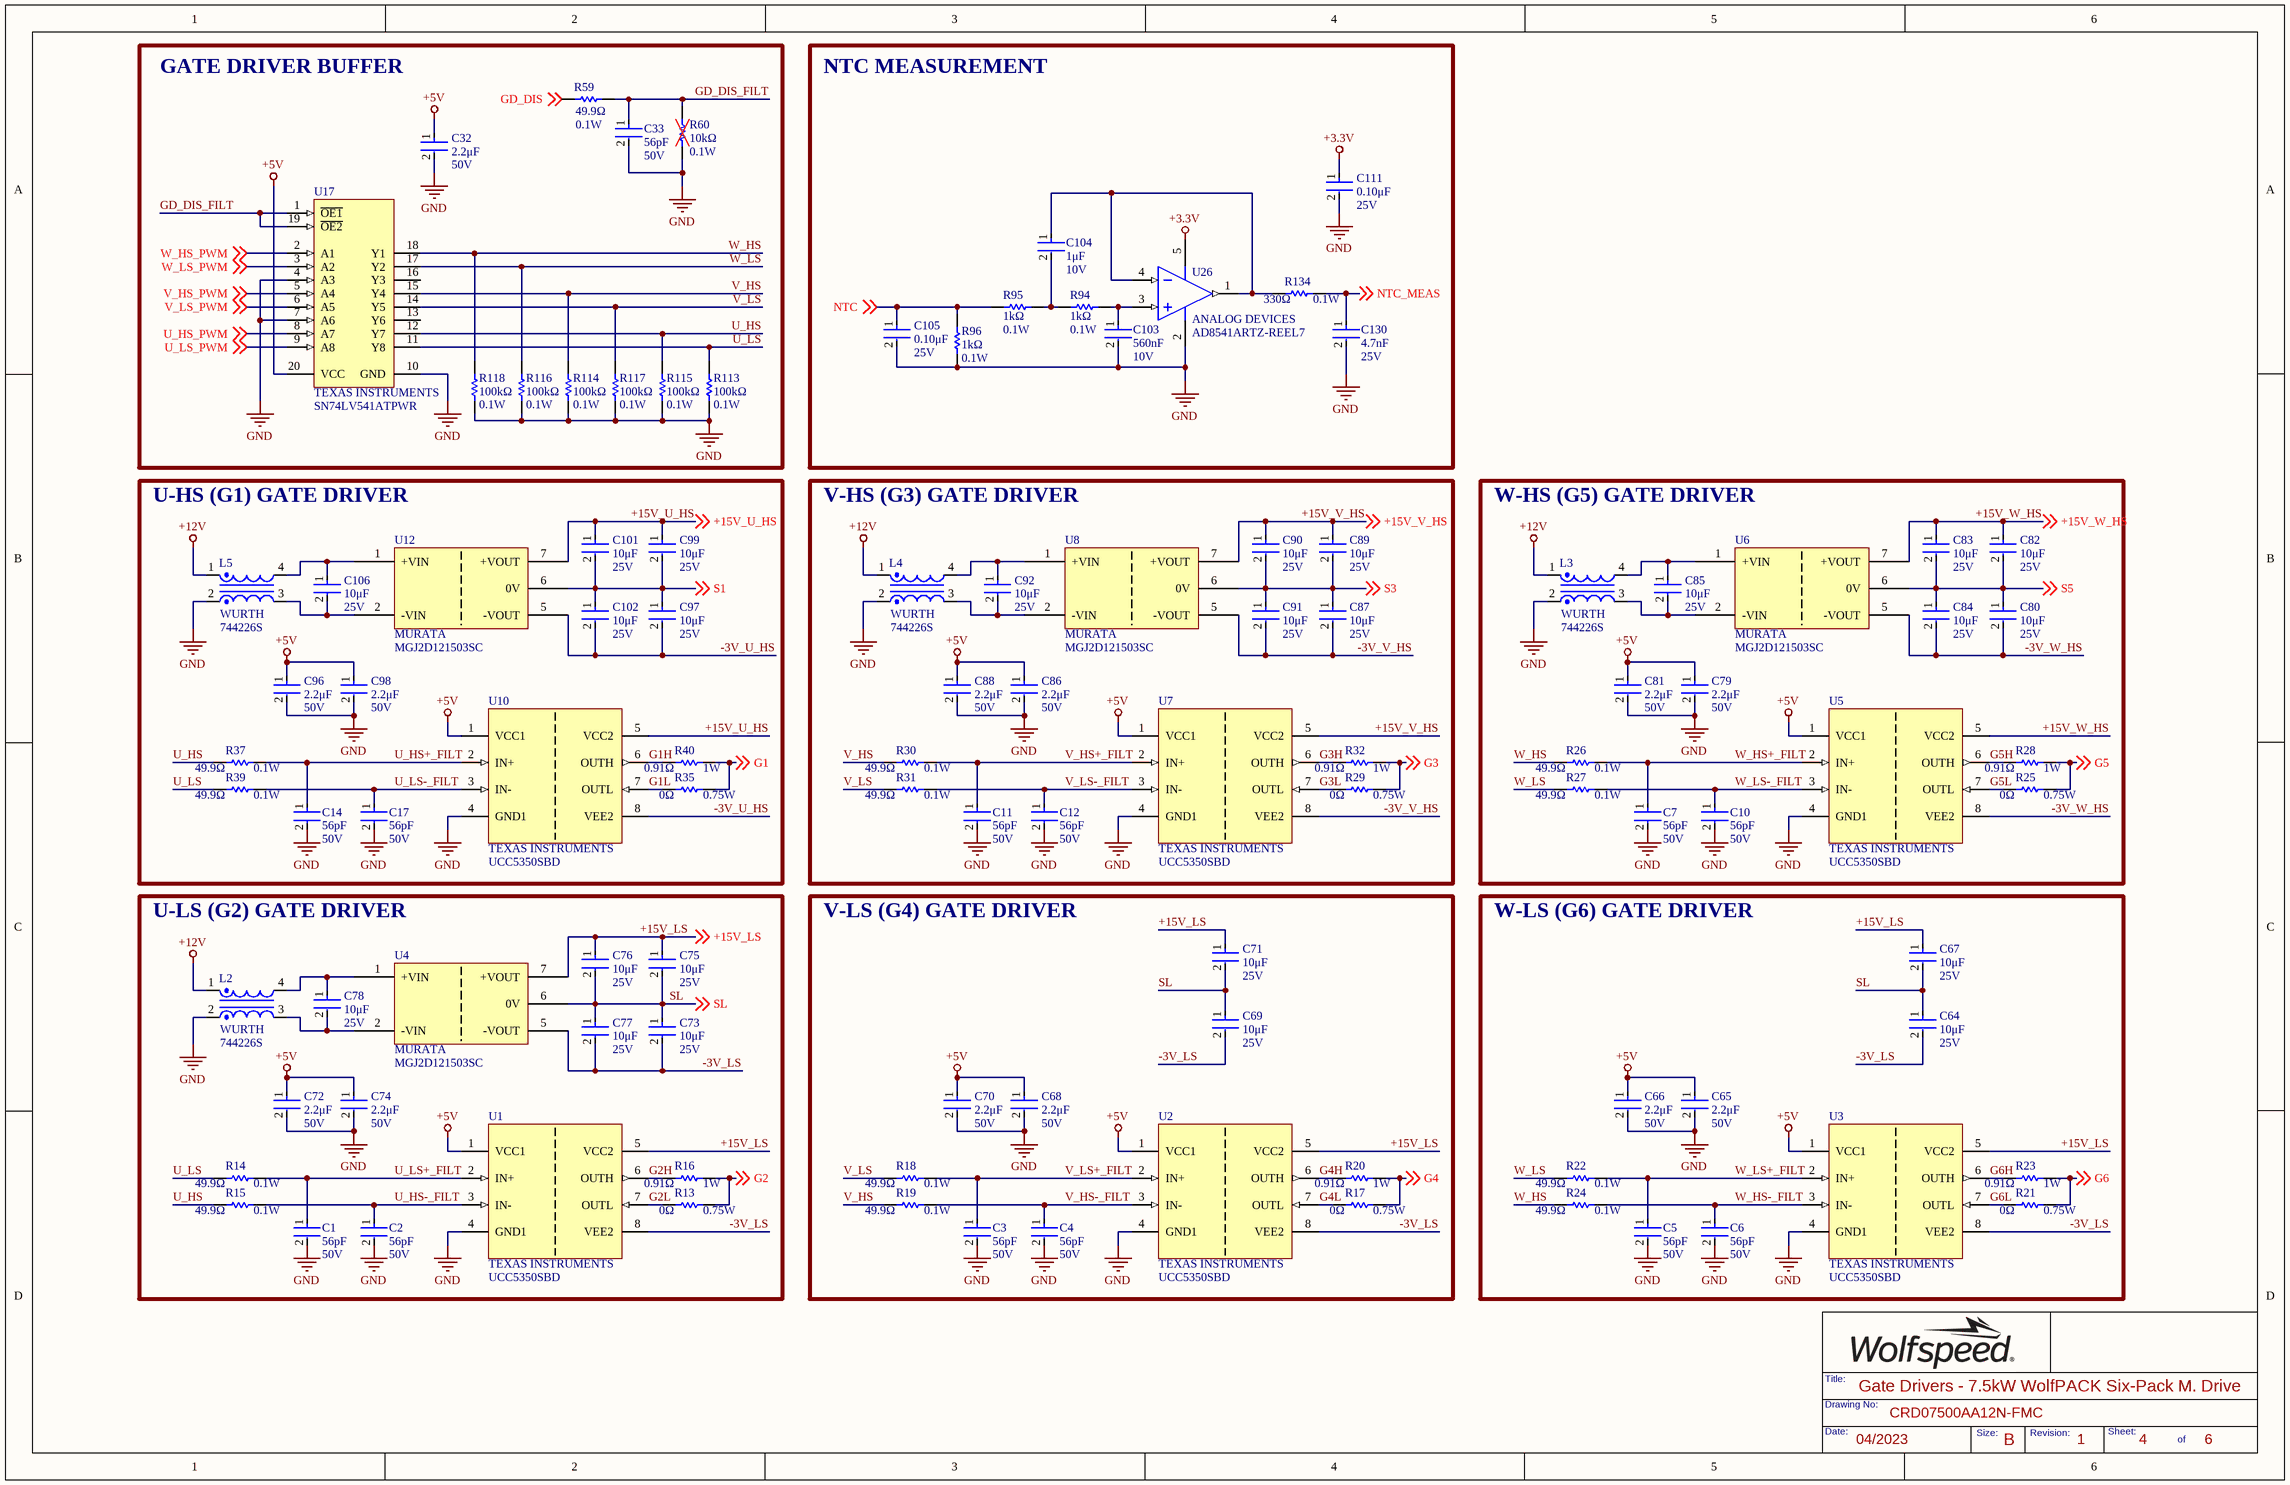
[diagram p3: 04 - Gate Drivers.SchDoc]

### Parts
C1  Capacitance: 56pF  Voltage Rating: 50V  [FP-C0603C-CF-IPC_B]  (hidden comment: CL10C560JB8NNNC)
C2  Capacitance: 56pF  Voltage Rating: 50V  [FP-C0603C-CF-IPC_B]  (hidden comment: CL10C560JB8NNNC)
C3  Capacitance: 56pF  Voltage Rating: 50V  [FP-C0603C-CF-IPC_B]  (hidden comment: CL10C560JB8NNNC)
C4  Capacitance: 56pF  Voltage Rating: 50V  [FP-C0603C-CF-IPC_B]  (hidden comment: CL10C560JB8NNNC)
C5  Capacitance: 56pF  Voltage Rating: 50V  [FP-C0603C-CF-IPC_B]  (hidden comment: CL10C560JB8NNNC)
C6  Capacitance: 56pF  Voltage Rating: 50V  [FP-C0603C-CF-IPC_B]  (hidden comment: CL10C560JB8NNNC)
C7  Capacitance: 56pF  Voltage Rating: 50V  [FP-C0603C-CF-IPC_B]  (hidden comment: CL10C560JB8NNNC)
C10  Capacitance: 56pF  Voltage Rating: 50V  [FP-C0603C-CF-IPC_B]  (hidden comment: CL10C560JB8NNNC)
C11  Capacitance: 56pF  Voltage Rating: 50V  [FP-C0603C-CF-IPC_B]  (hidden comment: CL10C560JB8NNNC)
C12  Capacitance: 56pF  Voltage Rating: 50V  [FP-C0603C-CF-IPC_B]  (hidden comment: CL10C560JB8NNNC)
C14  Capacitance: 56pF  Voltage Rating: 50V  [FP-C0603C-CF-IPC_B]  (hidden comment: CL10C560JB8NNNC)
C17  Capacitance: 56pF  Voltage Rating: 50V  [FP-C0603C-CF-IPC_B]  (hidden comment: CL10C560JB8NNNC)
C32  Voltage Rating: 50V  Capacitance: 2.2μF  [FP-C0603C-CF-IPC_B]  (hidden comment: GRT188R61H225ME13D)
C33  Capacitance: 56pF  Voltage Rating: 50V  [FP-C0603C-CF-IPC_B]  (hidden comment: CL10C560JB8NNNC)
C64  Voltage Rating: 25V  Capacitance: 10μF  [FP-CL31-IPC_B]  (hidden comment: CL31B106KAHSFNE)
C65  Voltage Rating: 50V  Capacitance: 2.2μF  [FP-C0603C-CF-IPC_B]  (hidden comment: GRT188R61H225ME13D)
C66  Voltage Rating: 50V  Capacitance: 2.2μF  [FP-C0603C-CF-IPC_B]  (hidden comment: GRT188R61H225ME13D)
C67  Voltage Rating: 25V  Capacitance: 10μF  [FP-CL31-IPC_B]  (hidden comment: CL31B106KAHSFNE)
C68  Voltage Rating: 50V  Capacitance: 2.2μF  [FP-C0603C-CF-IPC_B]  (hidden comment: GRT188R61H225ME13D)
C69  Voltage Rating: 25V  Capacitance: 10μF  [FP-CL31-IPC_B]  (hidden comment: CL31B106KAHSFNE)
C70  Voltage Rating: 50V  Capacitance: 2.2μF  [FP-C0603C-CF-IPC_B]  (hidden comment: GRT188R61H225ME13D)
C71  Voltage Rating: 25V  Capacitance: 10μF  [FP-CL31-IPC_B]  (hidden comment: CL31B106KAHSFNE)
C72  Voltage Rating: 50V  Capacitance: 2.2μF  [FP-C0603C-CF-IPC_B]  (hidden comment: GRT188R61H225ME13D)
C73  Voltage Rating: 25V  Capacitance: 10μF  [FP-CL31-IPC_B]  (hidden comment: CL31B106KAHSFNE)
C74  Voltage Rating: 50V  Capacitance: 2.2μF  [FP-C0603C-CF-IPC_B]  (hidden comment: GRT188R61H225ME13D)
C75  Voltage Rating: 25V  Capacitance: 10μF  [FP-CL31-IPC_B]  (hidden comment: CL31B106KAHSFNE)
C76  Voltage Rating: 25V  Capacitance: 10μF  [FP-CL31-IPC_B]  (hidden comment: CL31B106KAHSFNE)
C77  Voltage Rating: 25V  Capacitance: 10μF  [FP-CL31-IPC_B]  (hidden comment: CL31B106KAHSFNE)
C78  Voltage Rating: 25V  Capacitance: 10μF  [FP-CL31-IPC_B]  (hidden comment: CL31B106KAHSFNE)
C79  Voltage Rating: 50V  Capacitance: 2.2μF  [FP-C0603C-CF-IPC_B]  (hidden comment: GRT188R61H225ME13D)
C80  Voltage Rating: 25V  Capacitance: 10μF  [FP-CL31-IPC_B]  (hidden comment: CL31B106KAHSFNE)
C81  Voltage Rating: 50V  Capacitance: 2.2μF  [FP-C0603C-CF-IPC_B]  (hidden comment: GRT188R61H225ME13D)
C82  Voltage Rating: 25V  Capacitance: 10μF  [FP-CL31-IPC_B]  (hidden comment: CL31B106KAHSFNE)
C83  Voltage Rating: 25V  Capacitance: 10μF  [FP-CL31-IPC_B]  (hidden comment: CL31B106KAHSFNE)
C84  Voltage Rating: 25V  Capacitance: 10μF  [FP-CL31-IPC_B]  (hidden comment: CL31B106KAHSFNE)
C85  Voltage Rating: 25V  Capacitance: 10μF  [FP-CL31-IPC_B]  (hidden comment: CL31B106KAHSFNE)
C86  Voltage Rating: 50V  Capacitance: 2.2μF  [FP-C0603C-CF-IPC_B]  (hidden comment: GRT188R61H225ME13D)
C87  Voltage Rating: 25V  Capacitance: 10μF  [FP-CL31-IPC_B]  (hidden comment: CL31B106KAHSFNE)
C88  Voltage Rating: 50V  Capacitance: 2.2μF  [FP-C0603C-CF-IPC_B]  (hidden comment: GRT188R61H225ME13D)
C89  Voltage Rating: 25V  Capacitance: 10μF  [FP-CL31-IPC_B]  (hidden comment: CL31B106KAHSFNE)
C90  Voltage Rating: 25V  Capacitance: 10μF  [FP-CL31-IPC_B]  (hidden comment: CL31B106KAHSFNE)
C91  Voltage Rating: 25V  Capacitance: 10μF  [FP-CL31-IPC_B]  (hidden comment: CL31B106KAHSFNE)
C92  Voltage Rating: 25V  Capacitance: 10μF  [FP-CL31-IPC_B]  (hidden comment: CL31B106KAHSFNE)
C96  Voltage Rating: 50V  Capacitance: 2.2μF  [FP-C0603C-CF-IPC_B]  (hidden comment: GRT188R61H225ME13D)
C97  Voltage Rating: 25V  Capacitance: 10μF  [FP-CL31-IPC_B]  (hidden comment: CL31B106KAHSFNE)
C98  Voltage Rating: 50V  Capacitance: 2.2μF  [FP-C0603C-CF-IPC_B]  (hidden comment: GRT188R61H225ME13D)
C99  Voltage Rating: 25V  Capacitance: 10μF  [FP-CL31-IPC_B]  (hidden comment: CL31B106KAHSFNE)
C101  Voltage Rating: 25V  Capacitance: 10μF  [FP-CL31-IPC_B]  (hidden comment: CL31B106KAHSFNE)
C102  Voltage Rating: 25V  Capacitance: 10μF  [FP-CL31-IPC_B]  (hidden comment: CL31B106KAHSFNE)
C103  Capacitance: 560nF  Voltage Rating (DC): 10V  [FP-C0603C-CF-IPC_B]  (hidden comment: C0603C564K8PACTU)
C104  Capacitance: 1μF  Voltage Rating (DC): 10V  [FP-C0603C-CF-IPC_B]  (hidden comment: C0603C105K8RACTU)
C105  Voltage Rating: 25V  Capacitance: 0.10μF  [FP-C0603C-CF-IPC_B]  (hidden comment: C0603C104K3RACTU)
C106  Voltage Rating: 25V  Capacitance: 10μF  [FP-CL31-IPC_B]  (hidden comment: CL31B106KAHSFNE)
C111  Voltage Rating: 25V  Capacitance: 0.10μF  [FP-C0603C-CF-IPC_B]  (hidden comment: C0603C104K3RACTU)
C130  Capacitance: 4.7nF  Voltage Rating: 25V  [FP-C0603C-CF-IPC_B]  (hidden comment: C0603C472K3RAC7867)
L2  744226S  Manufacturer Print: WURTH  [WE-SL2]
L3  744226S  Manufacturer Print: WURTH  [WE-SL2]
L4  744226S  Manufacturer Print: WURTH  [WE-SL2]
L5  744226S  Manufacturer Print: WURTH  [WE-SL2]
R13  Resistance: 0Ω  Power Rating: 0.75W  [RESC3125X70X40NL20T20]  (hidden comment: CRCW12100000Z0EAHP)
R14  Resistance: 49.9Ω  Power Rating: 0.1W  [FP-MCR03-IPC_B]  (hidden comment: ERJ-3EKF49R9V)
R15  Resistance: 49.9Ω  Power Rating: 0.1W  [FP-MCR03-IPC_B]  (hidden comment: ERJ-3EKF49R9V)
R16  value 0.91Ω  Power: 1W  [RESC3125X70X40NL20T20]  (hidden comment: RCWE1210R910FKEA)
R17  Resistance: 0Ω  Power Rating: 0.75W  [RESC3125X70X40NL20T20]  (hidden comment: CRCW12100000Z0EAHP)
R18  Resistance: 49.9Ω  Power Rating: 0.1W  [FP-MCR03-IPC_B]  (hidden comment: ERJ-3EKF49R9V)
R19  Resistance: 49.9Ω  Power Rating: 0.1W  [FP-MCR03-IPC_B]  (hidden comment: ERJ-3EKF49R9V)
R20  value 0.91Ω  Power: 1W  [RESC3125X70X40NL20T20]  (hidden comment: RCWE1210R910FKEA)
R21  Resistance: 0Ω  Power Rating: 0.75W  [RESC3125X70X40NL20T20]  (hidden comment: CRCW12100000Z0EAHP)
R22  Resistance: 49.9Ω  Power Rating: 0.1W  [FP-MCR03-IPC_B]  (hidden comment: ERJ-3EKF49R9V)
R23  value 0.91Ω  Power: 1W  [RESC3125X70X40NL20T20]  (hidden comment: RCWE1210R910FKEA)
R24  Resistance: 49.9Ω  Power Rating: 0.1W  [FP-MCR03-IPC_B]  (hidden comment: ERJ-3EKF49R9V)
R25  Resistance: 0Ω  Power Rating: 0.75W  [RESC3125X70X40NL20T20]  (hidden comment: CRCW12100000Z0EAHP)
R26  Resistance: 49.9Ω  Power Rating: 0.1W  [FP-MCR03-IPC_B]  (hidden comment: ERJ-3EKF49R9V)
R27  Resistance: 49.9Ω  Power Rating: 0.1W  [FP-MCR03-IPC_B]  (hidden comment: ERJ-3EKF49R9V)
R28  value 0.91Ω  Power: 1W  [RESC3125X70X40NL20T20]  (hidden comment: RCWE1210R910FKEA)
R29  Resistance: 0Ω  Power Rating: 0.75W  [RESC3125X70X40NL20T20]  (hidden comment: CRCW12100000Z0EAHP)
R30  Resistance: 49.9Ω  Power Rating: 0.1W  [FP-MCR03-IPC_B]  (hidden comment: ERJ-3EKF49R9V)
R31  Resistance: 49.9Ω  Power Rating: 0.1W  [FP-MCR03-IPC_B]  (hidden comment: ERJ-3EKF49R9V)
R32  value 0.91Ω  Power: 1W  [RESC3125X70X40NL20T20]  (hidden comment: RCWE1210R910FKEA)
R35  Resistance: 0Ω  Power Rating: 0.75W  [RESC3125X70X40NL20T20]  (hidden comment: CRCW12100000Z0EAHP)
R37  Resistance: 49.9Ω  Power Rating: 0.1W  [FP-MCR03-IPC_B]  (hidden comment: ERJ-3EKF49R9V)
R39  Resistance: 49.9Ω  Power Rating: 0.1W  [FP-MCR03-IPC_B]  (hidden comment: ERJ-3EKF49R9V)
R40  value 0.91Ω  Power: 1W  [RESC3125X70X40NL20T20]  (hidden comment: RCWE1210R910FKEA)
R59  Resistance: 49.9Ω  Power Rating: 0.1W  [FP-MCR03-IPC_B]  (hidden comment: ERJ-3EKF49R9V)
R60  Resistance: 10kΩ  Max Power Dissipation: 0.1W  [FP-MCR03-IPC_B]  (hidden comment: ERJ3EKF1002V)
R94  Resistance: 1kΩ  Power Rating: 0.1W  [FP-MCR03-IPC_B]  (hidden comment: RT0603DRD071KL)
R95  Resistance: 1kΩ  Power Rating: 0.1W  [FP-MCR03-IPC_B]  (hidden comment: RT0603DRD071KL)
R96  Resistance: 1kΩ  Power Rating: 0.1W  [FP-MCR03-IPC_B]  (hidden comment: RT0603DRD071KL)
R113  Resistance: 100kΩ  Power Rating: 0.1W  [FP-MCR03-IPC_B]  (hidden comment: RC0603FR-07100KL)
R114  Resistance: 100kΩ  Power Rating: 0.1W  [FP-MCR03-IPC_B]  (hidden comment: RC0603FR-07100KL)
R115  Resistance: 100kΩ  Power Rating: 0.1W  [FP-MCR03-IPC_B]  (hidden comment: RC0603FR-07100KL)
R116  Resistance: 100kΩ  Power Rating: 0.1W  [FP-MCR03-IPC_B]  (hidden comment: RC0603FR-07100KL)
R117  Resistance: 100kΩ  Power Rating: 0.1W  [FP-MCR03-IPC_B]  (hidden comment: RC0603FR-07100KL)
R118  Resistance: 100kΩ  Power Rating: 0.1W  [FP-MCR03-IPC_B]  (hidden comment: RC0603FR-07100KL)
R134  Resistance: 330Ω  Max Power Dissipation: 0.1W  [FP-MCR03-IPC_B]  (hidden comment: RC0603FR-07330RL)
U1  UCC5350SBD  Manufacturer Print: TEXAS INSTRUMENTS  [D0008B_HV]
U2  UCC5350SBD  Manufacturer Print: TEXAS INSTRUMENTS  [D0008B_HV]
U3  UCC5350SBD  Manufacturer Print: TEXAS INSTRUMENTS  [D0008B_HV]
U4  MGJ2D121503SC  Manufacturer Print: MURATA  [MGJ2D121509SC]
U5  UCC5350SBD  Manufacturer Print: TEXAS INSTRUMENTS  [D0008B_HV]
U6  MGJ2D121503SC  Manufacturer Print: MURATA  [MGJ2D121509SC]
U7  UCC5350SBD  Manufacturer Print: TEXAS INSTRUMENTS  [D0008B_HV]
U8  MGJ2D121503SC  Manufacturer Print: MURATA  [MGJ2D121509SC]
U10  UCC5350SBD  Manufacturer Print: TEXAS INSTRUMENTS  [D0008B_HV]
U12  MGJ2D121503SC  Manufacturer Print: MURATA  [MGJ2D121509SC]
U17  Manufacturer: TEXAS INSTRUMENTS  [PW0020A_L]  (hidden comment: SN74LV541ATPWR)
U26  AD8541ARTZ-REEL7  Manufacturer: ANALOG DEVICES  [ADI-RJ-5_N]

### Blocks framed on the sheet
GATE DRIVER BUFFER: C32 C33 R59 R60 R113-R118 U17
NTC MEASUREMENT: C103-C105 C111 C130 R94-R96 R134 U26
U-HS (G1) GATE DRIVER: C14 C17 C96-C99 C101 C102 C106 L5 R35 R37 R39 R40 U10 U12
V-HS (G3) GATE DRIVER: C11 C12 C86-C92 L4 R29-R32 U7 U8
W-HS (G5) GATE DRIVER: C7 C10 C79-C85 L3 R25-R28 U5 U6
U-LS (G2) GATE DRIVER: C1 C2 C72-C78 L2 R13-R16 U1 U4
V-LS (G4) GATE DRIVER: C3 C4 C68-C71 R17-R20 U2
W-LS (G6) GATE DRIVER: C5 C6 C64-C67 R21-R24 U3

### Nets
+3.3V: C111.1 U26.5(+V)
+5V: C32.1 C65.1 C66.1 C68.1 C70.1 C72.1 C74.1 C79.1 C81.1 C86.1 C88.1 C96.1 C98.1 U1.1(VCC1) U2.1(VCC1) U3.1(VCC1) U5.1(VCC1) U7.1(VCC1) U10.1(VCC1) U17.20(VCC)
+12V: L2.1 L3.1 L4.1 L5.1
GND: C1.2 C2.2 C3.2 C4.2 C5.2 C6.2 C7.2 C10.2 C11.2 C12.2 C14.2 C17.2 C32.2 C33.2 C65.2 C66.2 C68.2 C70.2 C72.2 C74.2 C79.2 C81.2 C86.2 C88.2 C96.2 C98.2 C103.2 C105.2 C111.2 C130.2 L2.2 L3.2 L4.2 L5.2 R60.1 R96.1 R113.1 R114.1 R115.1 R116.1 R117.1 R118.1 U1.4(GND1) U2.4(GND1) U3.4(GND1) U5.4(GND1) U7.4(GND1) U10.4(GND1) U17.4(A3) U17.7(A6) U17.10(GND) U26.2(-V)
+15V_LS: C67.1 C71.1 C75.1 C76.1 U1.5(VCC2) U2.5(VCC2) U3.5(VCC2) U4.7(+VOUT) ; off-sheet +15V_LS
+15V_U_HS: C99.1 C101.1 U10.5(VCC2) U12.7(+VOUT) ; off-sheet +15V_U_HS
+15V_V_HS: C89.1 C90.1 U7.5(VCC2) U8.7(+VOUT) ; off-sheet +15V_V_HS
+15V_W_HS: C82.1 C83.1 U5.5(VCC2) U6.7(+VOUT) ; off-sheet +15V_W_HS
-3V_LS: C64.2 C69.2 C73.2 C77.2 U1.8(VEE2) U2.8(VEE2) U3.8(VEE2) U4.5(-VOUT)
-3V_U_HS: C97.2 C102.2 U10.8(VEE2) U12.5(-VOUT)
-3V_V_HS: C87.2 C91.2 U7.8(VEE2) U8.5(-VOUT)
-3V_W_HS: C80.2 C84.2 U5.8(VEE2) U6.5(-VOUT)
G1: R35.2 R40.2 ; off-sheet G1
G1H: R40.1 U10.6(OUTH)
G1L: R35.1 U10.7(OUTL)
G2: R13.2 R16.2 ; off-sheet G2
G2H: R16.1 U1.6(OUTH)
G2L: R13.1 U1.7(OUTL)
G3: R29.2 R32.2 ; off-sheet G3
G3H: R32.1 U7.6(OUTH)
G3L: R29.1 U7.7(OUTL)
G4: R17.2 R20.2 ; off-sheet G4
G4H: R20.1 U2.6(OUTH)
G4L: R17.1 U2.7(OUTL)
G5: R25.2 R28.2 ; off-sheet G5
G5H: R28.1 U5.6(OUTH)
G5L: R25.1 U5.7(OUTL)
G6: R21.2 R23.2 ; off-sheet G6
G6H: R23.1 U3.6(OUTH)
G6L: R21.1 U3.7(OUTL)
GD_DIS: R59.1 ; off-sheet GD_DIS
GD_DIS_FILT: C33.1 R59.2 R60.2 U17.1(~{OE1}) U17.19(~{OE2})
NTC: C105.1 R95.1 R96.2 ; off-sheet NTC
NTC_MEAS: C130.1 R134.2 ; off-sheet NTC_MEAS
S1: C97.1 C99.2 C101.2 C102.1 U12.6(0V) ; off-sheet S1
S3: C87.1 C89.2 C90.2 C91.1 U8.6(0V) ; off-sheet S3
S5: C80.1 C82.2 C83.2 C84.1 U6.6(0V) ; off-sheet S5
SL: C64.1 C67.2 C69.1 C71.2 C73.1 C75.2 C76.2 C77.1 U4.6(0V) ; off-sheet SL
U_HS: R15.1 R37.1 R115.2 U17.12(Y7)
U_HS+_FILT: C14.1 R37.2 U10.2(IN+)
U_HS-_FILT: C2.1 R15.2 U1.3(IN-)
U_HS_PWM: U17.8(A7) ; off-sheet U_HS_PWM
U_LS: R14.1 R39.1 R113.2 U17.11(Y8)
U_LS+_FILT: C1.1 R14.2 U1.2(IN+)
U_LS-_FILT: C17.1 R39.2 U10.3(IN-)
U_LS_PWM: U17.9(A8) ; off-sheet U_LS_PWM
V_HS: R19.1 R30.1 R114.2 U17.15(Y4)
V_HS+_FILT: C11.1 R30.2 U7.2(IN+)
V_HS-_FILT: C4.1 R19.2 U2.3(IN-)
V_HS_PWM: U17.5(A4) ; off-sheet V_HS_PWM
V_LS: R18.1 R31.1 R117.2 U17.14(Y5)
V_LS+_FILT: C3.1 R18.2 U2.2(IN+)
V_LS-_FILT: C12.1 R31.2 U7.3(IN-)
V_LS_PWM: U17.6(A5) ; off-sheet V_LS_PWM
W_HS: R24.1 R26.1 R118.2 U17.18(Y1)
W_HS+_FILT: C7.1 R26.2 U5.2(IN+)
W_HS-_FILT: C6.1 R24.2 U3.3(IN-)
W_HS_PWM: U17.2(A1) ; off-sheet W_HS_PWM
W_LS: R22.1 R27.1 R116.2 U17.17(Y2)
W_LS+_FILT: C5.1 R22.2 U3.2(IN+)
W_LS-_FILT: C10.1 R27.2 U5.3(IN-)
W_LS_PWM: U17.3(A2) ; off-sheet W_LS_PWM
NetC78_1: C78.1 L2.4 U4.1(+VIN)
NetC78_2: C78.2 L2.3 U4.2(-VIN)
NetC85_1: C85.1 L3.4 U6.1(+VIN)
NetC85_2: C85.2 L3.3 U6.2(-VIN)
NetC92_1: C92.1 L4.4 U8.1(+VIN)
NetC92_2: C92.2 L4.3 U8.2(-VIN)
NetC103_1: C103.1 R94.2 U26.3(+IN_A)
NetC104_1: C104.1 R134.1 U26.1(OUT_A) U26.4(-IN_A)
NetC104_2: C104.2 R94.1 R95.2
NetC106_1: C106.1 L5.4 U12.1(+VIN)
NetC106_2: C106.2 L5.3 U12.2(-VIN)

Not connected (* = marked no-connect by the designer): U17 13(Y6) 16(Y3)

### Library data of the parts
C1-C7 C10-C12 C14 C17 C33 = CL10C560JB8NNNC: CAP CER 56PF 50V C0G/NP0 0603; Manufacturer: SAMSUNG; Material: Ceramic; Tolerance: 5%; Dielectric: C0G; Temperature Coefficient: 30ppm/°C
C32 C65 C66 C68 C70 C72 C74 C79 C81 C86 C88 C96 C98 = GRT188R61H225ME13D: CAP CER 2.2UF 50V X5R 0603; Manufacturer: MURATA; Tolerance: 20%; Value: 2.2μF
C64 C67 C69 C71 C73 C75-C78 C80 C82-C85 C87 C89-C92 C97 C99 C101 C102 C106 = CMP-13271-001434-1: CAP CER 10UF 25V X7R 1206; Manufacturer: SAMSUNG; Tolerance: 10%; Value: 10μF
C103 = C0603C564K8PACTU: CAP CER 0.56UF 10V X5R 0603; Manufacturer: KEMET; Dielectric Material: Ceramic; Tolerance: 10%; Value: 560nF
C104 = C0603C105K8RACTU: CAP CER 1UF 10V X7R 0603; Manufacturer: KEMET; Dielectric Material: Ceramic; Tolerance: 10%; Dissipation Factor: 5%; Value: 1μF
C105 C111 = CMP-2006-03057-2: as C121 on sheet 02 - Power Stage
C130 = C0603C472K3RAC7867: CAP CER 4700PF 25V 10% X7R 0603; Manufacturer: KEMET; Manufacturer Part Number: C0603C472K3RACTU; Dielectric Material: Ceramic; Value: 4.7nF
L2-L5 = 744226S: CMC 10UH 1.6A 2LN 920 OHM SMD; Tolerance: 30%; Voltage Rating: 80V; Resistance: 80mR; Impedance: 920R; Number of Lines: 2; Test Frequency: 1kHz; Value: 10μH
R13 R17 R21 R25 R29 R35 = CRCW12100000Z0EAHP: RES SMD 0 OHM JUMPER 3/4W 1210; Manufacturer: VISHAY; Description: CRCW Series 1210 0 Ohm JUMPER Thick Film Chip Resistor; Max Power Dissipation: 750mW
R14 R15 R18 R19 R22 R24 R26 R27 R30 R31 R37 R39 R59 = ERJ-3EKF49R9V: RES SMD 49.9 OHM 1% 1/10W 0603; Manufacturer: PANASONIC; Temperature Coefficient: 100ppm/°C; Voltage Rating: 75V; Max Power Dissipation: 100mW; Voltage Rating (DC): 50V; Working Voltage: 6V; Value: 49.9Ω
R16 R20 R23 R28 R32 R40 = CMP-2005-02198-1: RES 0.91 OHM 1% 1W 1210; Manufacturer: VISHAY
R60 = ERJ3EKF1002V: RES SMD 10K OHM 1% 1/10W 0603; Manufacturer: PANASONIC; Manufacturer Part Number: ERJ-3EKF1002V; Temperature Coefficient: 100ppm/°C; Power Rating: 100mW; Voltage Rating: 75V; Value: 10kΩ
R94-R96 = RT0603DRD071KL: as R78 on sheet 03 - Controller
R113-R118 = RC0603FR-07100KL: RES 100K OHM 1% 1/10W 0603; Manufacturer: YAGEO; Temperature Coefficient: 100ppm/°C; Voltage Rating: 50V; Working Voltage: 75V; Max Power Dissipation: 100mW; Value: 100kΩ
R134 = RC0603FR-07330RL: RES 330 OHM 1% 1/10W 0603; Manufacturer: YAGEO; Temperature Coefficient: 100ppm/°C; Power Rating: 100mW; Voltage Rating: 50V; Value: 330Ω
U1-U3 U5 U7 U10 = UCC5350SBD: 5A/5A, 3-KVRMS SINGLE-CHANNEL IS; Class: U; Working Voltage: 990V; Number of Channels: 1
U4 U6 U8 U12 = MGJ2D121503SC: DC DC CONVERTER 15V -3V 1.7W
U17 = CMP-0440-01163-3: IC BUF NON-INVERT 5.5V 20TSSOP; Bits(#): 8; Voltage(Nom)(V): 5; ICC @ Nom Voltage(Max)(mA): 0.02; VCC(Max)(V): 5.5; Output Type: CMOS; Rating: Catalog; Input Type: TTL; VCC(Min)(V): 4.5; F @ Nom Voltage(Max)(Mhz): 110; tpd @ Nom Voltage(Max)(ns): 7.9
U26 = CMP-0384-01498-2: IC OPAMP GP 1 CIRCUIT SOT23-5; Generic Part Number: AD8541; Slew Rate: 920mV/us; Input Bias Current: 4pA; V Span Max: 5.5V; Amplifiers Per Package: 1; Small Signal Bandwidth: 1MHz; Input Offset Voltage: 1mV; Iq/Amp: 65uA; V Span Min: 2.7V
